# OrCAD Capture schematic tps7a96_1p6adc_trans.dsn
size A
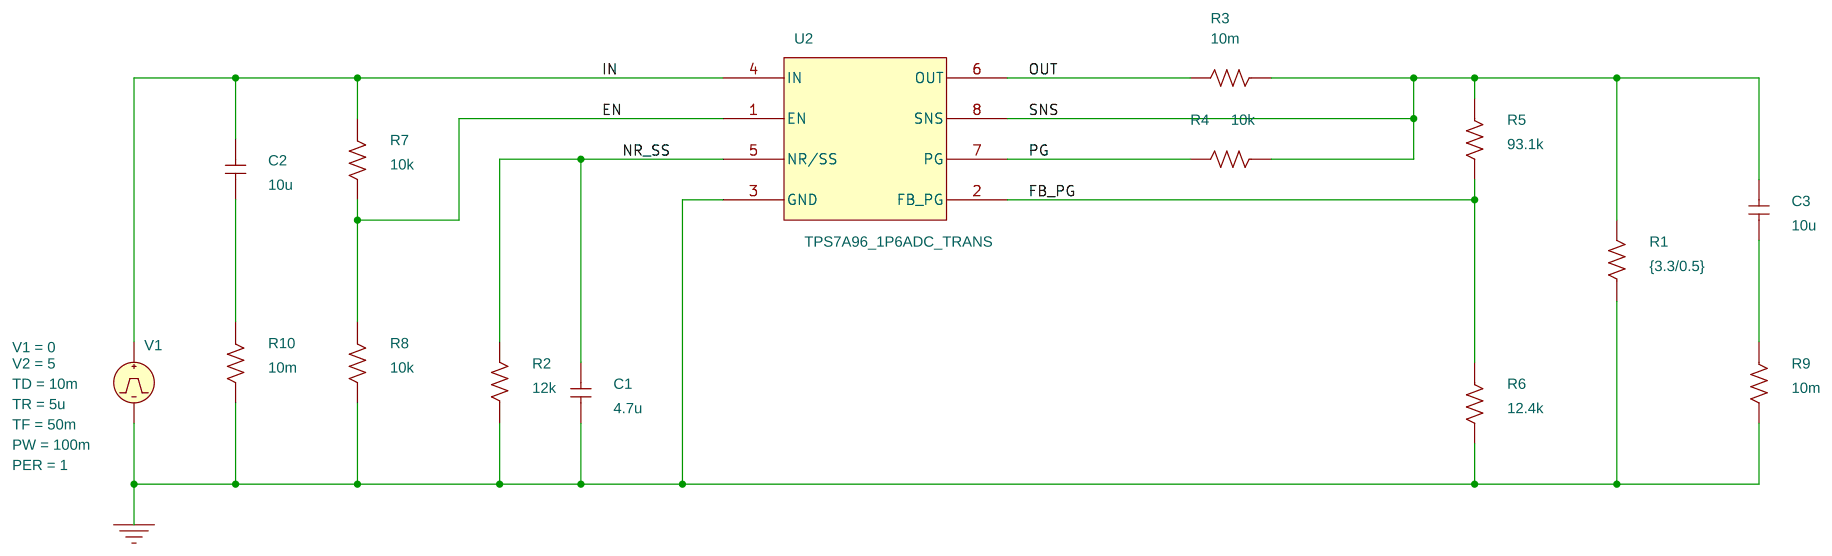
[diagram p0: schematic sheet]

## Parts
C1  4.7u  [RAD/CK05]
C2  10u  [RAD/CK05]
C3  10u  [RAD/CK05]
R1  {3.3/0.5}  [AX/RC05]
R2  12k  [AX/RC05]
R3  10m  [AX/RC05]
R4  10k  [AX/RC05]
R5  93.1k  [AX/RC05]
R6  12.4k  [AX/RC05]
R7  10k  [AX/RC05]
R8  10k  [AX/RC05]
R9  10m  [AX/RC05]
R10  10m  [AX/RC05]
U2  TPS7A96_1P6ADC_TRANS
V1  VPULSE

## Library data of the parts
C1-C3 = C
R1-R10 = R
U2 = TPS7A94_1ADC_TRANS_2: PSpiceTemplate: X^@REFDES  %EN %FB_PG %GND %IN %NR/SS %OUT %PG %SNS @MODEL
V1 = VPULSE: PER: 1; PW: 100m; TD: 10m; TF: 50m; TR: 5u; V1: 0; V2: 5

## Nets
0: C1.1 R1.1 R2.1 R6.2 R8.2 R9.2 R10.2 U2.3(GND) V1.2(-)
EN: R7.2 R8.1 U2.1(EN)
FB_PG: R5.2 R6.1 U2.2(FB_PG)
IN: C2.2 R7.1 U2.4(IN) V1.1(+)
NR_SS: C1.2 R2.2 U2.5(NR/SS)
OUT: R3.2 U2.6(OUT)
PG: R4.2 U2.7(PG)
SNS: C3.2 R1.2 R3.1 R4.1 R5.1 U2.8(SNS)
N240913: C2.1 R10.1
N241023: C3.1 R9.1
